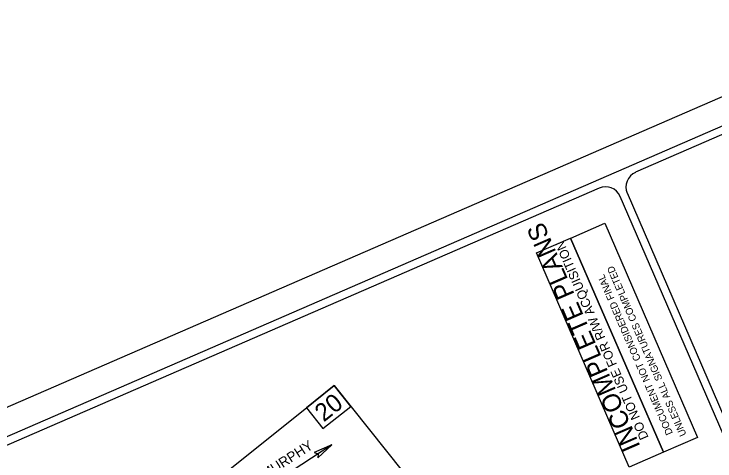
# Model space of a CAD drawing. Extents: x 442728 to 492797, y 479541 to 511293.
# Drawn here: x 471810 to 478444, y 507069 to 511293 of the extents above; entities that cross this region are included whole.
import ezdxf

# ---------------------------------------------------------------- set-up
doc = ezdxf.new("R2010")
doc.units = 0
for name, color, linetype in [('Default', 7, 'Continuous'), ('Prop PHM Terminator Cell', 7, 'Continuous'), ('Sheet Plan Layout CELL', 7, 'Continuous'), ('Sheet Plot Border Outside CELL', 7, 'Continuous'), ('Sheet Sticker Exception Certification CELL', 7, 'Continuous'), ('Sheet Sticker Incomplete CELL', 7, 'Continuous'), ('Sheet Title CELL', 7, 'Continuous')]:
    doc.layers.add(name, color=color, linetype=linetype)

# ---------------------------------------------------------------- blocks, each defined once
blk = doc.blocks.new('PHM Terminator')
at = {"layer": 'Prop PHM Terminator Cell'}
blk.add_lwpolyline([(-9, 1.55), (0, 0), (-9.05, -1.6), (-7.9, 0)], close=True, dxfattribs=at)

msp = doc.modelspace()

# ---------------------------------------------------------------- linework, layer by layer
at = {"layer": 'Default'}
msp.add_line((474818.3, 507220.6), (474060.3, 506729.9), dxfattribs=at)
at = {"layer": 'Sheet Plan Layout CELL'}
for points in [[(474323.6, 506023.7), (473667.4, 506843.6), (474545.8, 507546.5), (474545.8, 507546.5), (474838.6, 507780.8), (475494.7, 506961)], [(474733.8, 507374.4), (474995.9, 507584.1), (474838.6, 507780.8), (474576.4, 507571)]]:
    msp.add_lwpolyline(points, close=True, dxfattribs=at)
at = {"layer": 'Sheet Plot Border Outside CELL'}
msp.add_lwpolyline([(465175.4, 504729.3), (475224.7, 481554), (490362.8, 488118.1), (480313.5, 511293.4)], close=True, dxfattribs=at)
at = {"layer": 'Sheet Sticker Exception Certification CELL'}
for p, q in [((477078, 509175.2), (477401.4, 509315.4)), ((477401.3, 509315.3), (478278.5, 507292.3)), ((477955.1, 507152.1), (477077.9, 509175.1)), ((478278.5, 507292.3), (477955.1, 507152.1))]:
    msp.add_line(p, q, dxfattribs=at)
at = {"layer": 'Sheet Sticker Incomplete CELL'}
msp.add_lwpolyline([(477955.1, 507152.1), (477631.7, 507011.8), (476754.4, 509034.8), (477077.9, 509175.1)], close=True, dxfattribs=at)
at = {"layer": 'Sheet Title CELL'}
for p, q in [((486019.5, 490027.9), (477545.7, 509570)), ((478540.8, 507463.6), (477614.5, 509599.9))]:
    msp.add_line(p, q, dxfattribs=at)
for points in [[(479933.3, 510850.6), (465758.6, 504704.2)], [(479894.3, 510752), (477692.4, 509797.2)], [(477348.5, 509648.1), (465857, 504665.1)]]:
    msp.add_lwpolyline(points, dxfattribs=at)
for centre, start, end in [((477751.4, 509659.3), 113.44243, 203.44243), ((477407.4, 509510.2), 23.44243, 113.44243)]:
    msp.add_arc(centre, 150, start, end, dxfattribs=at)

# ---------------------------------------------------------------- block references
at = {"layer": 'Default', "xscale": 19.68750000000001, "yscale": -19.687500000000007, "rotation": 32.92159951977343}
msp.add_blockref('PHM Terminator', (474818.3, 507220.6), dxfattribs=at)

# ---------------------------------------------------------------- texts
at = {"layer": 'Default'}
msp.add_text('TO MURPHY', height=94.92, rotation=32.86087, dxfattribs=at).set_placement((474009.3, 506778.1))
at = {"layer": 'Sheet Plan Layout CELL'}
msp.add_text('20', height=168.74, rotation=38.66645, dxfattribs=at).set_placement((474741.4, 507431.8))
at = {"layer": 'Sheet Sticker Exception Certification CELL'}
for s, p in [('UNLESS ALL SIGNATURES COMPLETED', (478175.4, 507318.4)), ('DOCUMENT NOT CONSIDERED FINAL', (478046.5, 507331.4))]:
    msp.add_text(s, height=67.501, rotation=113.44243, dxfattribs=at).set_placement(p)
at = {"layer": 'Sheet Sticker Incomplete CELL'}
for s, height, p in [('INCOMPLETE PLANS', 172.802, (477740.6, 507205.4)), ('DO NOT USE FOR R/W ACQUISITION', 86.401, (477816.9, 507291.6))]:
    msp.add_text(s, height=height, rotation=113.44243, dxfattribs=at).set_placement(p)

doc.saveas('drawing.dxf')
